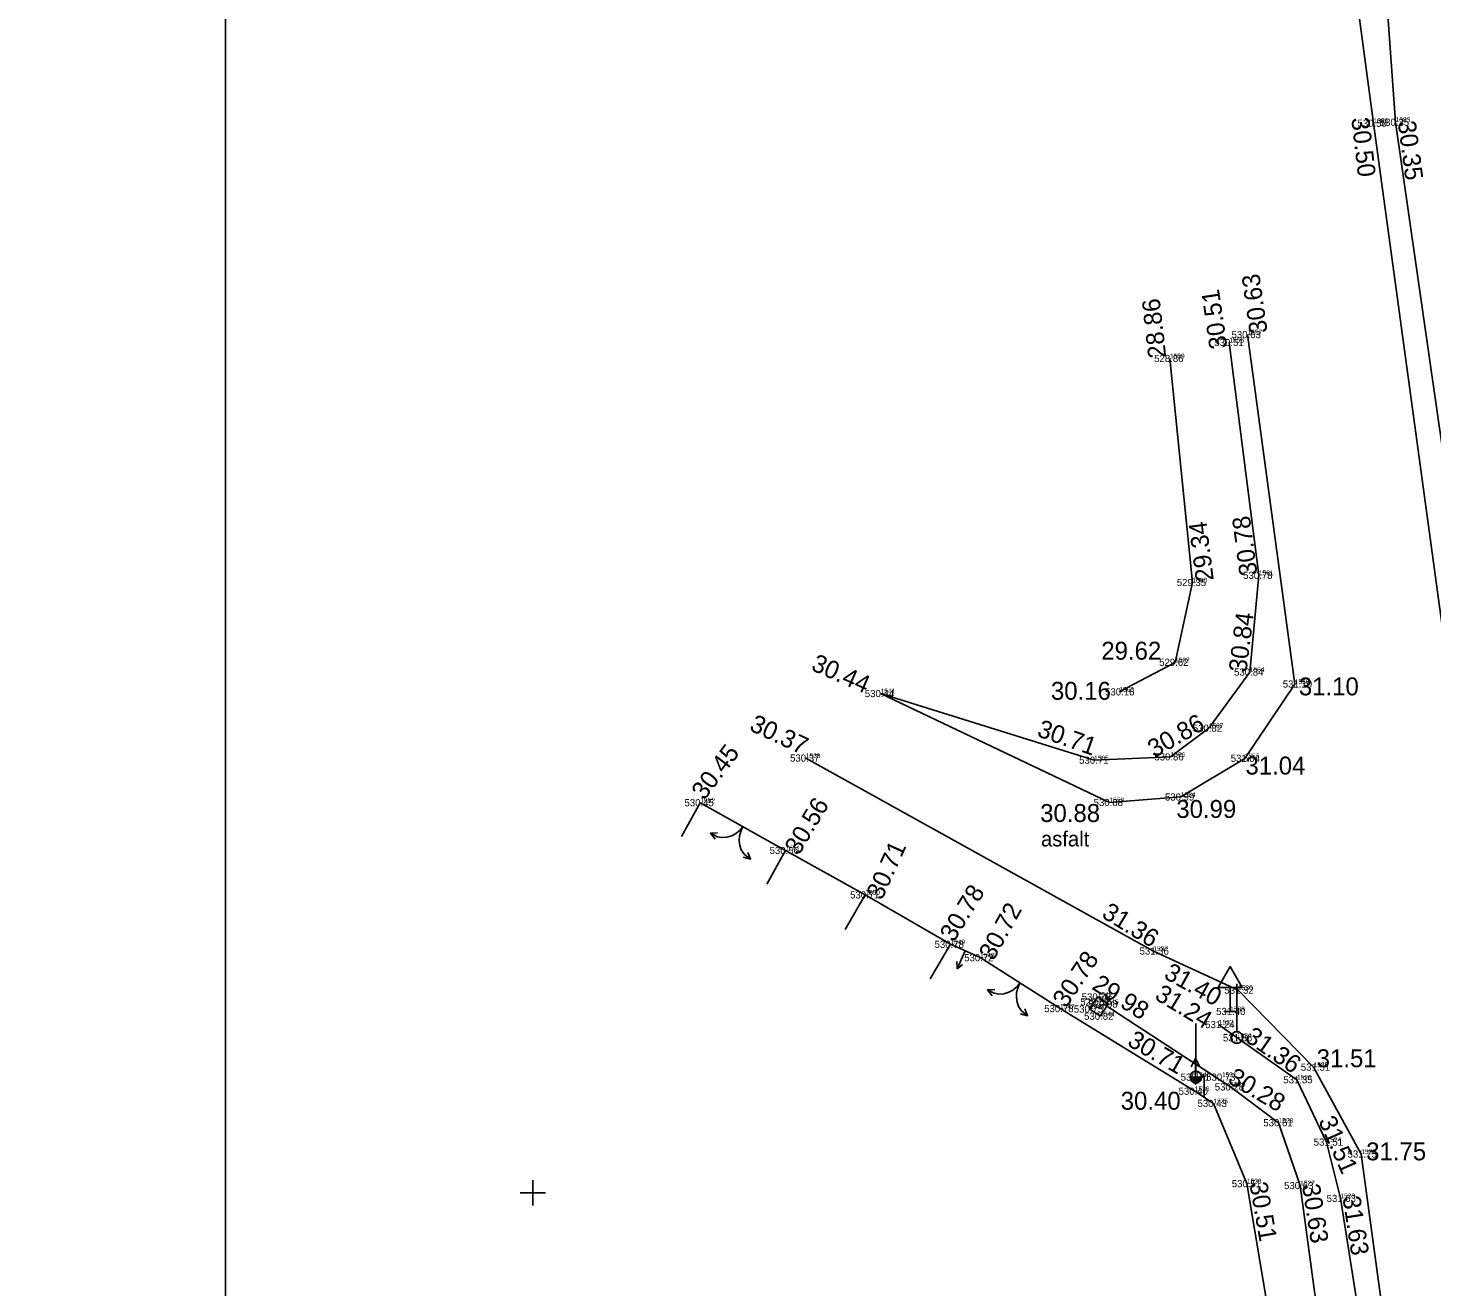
# Model space of a CAD drawing. Extents: x -866693 to -866303, y -1041966 to -1040244.
# Drawn here: x -866521.1 to -866462.4, y -1041903.9 to -1041851.2 of the extents above; entities that cross this region are included whole.
import ezdxf

# ---------------------------------------------------------------- set-up
doc = ezdxf.new("R2010")
doc.units = 0
for name, color, linetype in [('1 hrana zpevněné komunikace-plocha', 7, 'Continuous'), ('10 plot drátěný', 7, 'Continuous'), ('31 budova zděná', 7, 'Continuous'), ('32 stavba bez rozlišení', 7, 'Continuous'), ('33 vstup', 7, 'Continuous'), ('34 vrata-vjezd', 7, 'Continuous'), ('38 sloup dřevěný', 7, 'Continuous'), ('39 sloup betonový', 7, 'Continuous'), ('42 dopravní značka', 7, 'Continuous'), ('44 PRIS', 7, 'Continuous'), ('56 přítokové nebo odtokové potrubí', 7, 'Continuous'), ('7 hrana svah nahoře', 7, 'Continuous'), ('8 hrana svah dole', 7, 'Continuous'), ('9 plot dřevěný', 7, 'Continuous'), ('Bod', 7, 'Continuous'), ('Formát', 7, 'Continuous'), ('Nadmořská výška', 7, 'Continuous'), ('Nadmořská výška_tisk', 7, 'Continuous'), ('popisy', 7, 'Continuous'), ('Síť křížek', 7, 'Continuous'), ('Číslo bodu', 7, 'Continuous')]:
    doc.layers.add(name, color=color, linetype=linetype)

msp = doc.modelspace()

# ---------------------------------------------------------------- linework, layer by layer
at = {"layer": '1 hrana zpevněné komunikace-plocha'}
for points in [[(-866521.136, -1041445.078), (-866508.392, -1041537.454), (-866498.773, -1041606.69), (-866494.1, -1041640.595), (-866489.402, -1041674.676), (-866486.72, -1041694.284), (-866486.072, -1041699.754), (-866485.271, -1041705.651), (-866480.766, -1041738.663), (-866470.416, -1041813.512), (-866469.678, -1041818.801), (-866468.328, -1041828.98), (-866464.804, -1041855.208), (-866460.868, -1041884.031), (-866456.109, -1041894.798), (-866454.046, -1041896.659), (-866450.549, -1041899.657), (-866442.256, -1041905.958), (-866433.526, -1041913.041), (-866423.347, -1041921.351)], [(-866485.44, -1041879.086), (-866475.862, -1041883.647), (-866472.872, -1041883.42), (-866470.196, -1041881.804), (-866468.096, -1041878.694), (-866470.077, -1041864.06)], [(-866458.763, -1041945.697), (-866463.007, -1041915.39), (-866465.316, -1041898.37), (-866467.312, -1041894.734), (-866470.477, -1041891.508), (-866474.022, -1041889.87), (-866488.573, -1041881.791)]]:
    msp.add_lwpolyline(points, dxfattribs=at)
at = {"layer": '10 plot drátěný'}
for p, q in [((-866470.107, -1041899.606), (-866471.508, -1041896.249)), ((-866467.474, -1041915.319), (-866470.107, -1041899.606))]:
    msp.add_line(p, q, dxfattribs=at)
at = {"layer": '31 budova zděná'}
for p, q in [((-866492.992, -1041883.662), (-866493.781, -1041885.073)), ((-866492.337, -1041884.028), (-866492.992, -1041883.662)), ((-866489.422, -1041885.658), (-866490.206, -1041887.065)), ((-866489.422, -1041885.658), (-866490.077, -1041885.292)), ((-866486.085, -1041887.518), (-866489.422, -1041885.658)), ((-866486.085, -1041887.518), (-866486.929, -1041888.97)), ((-866482.522, -1041889.589), (-866486.085, -1041887.518)), ((-866482.522, -1041889.589), (-866483.366, -1041891.041))]:
    msp.add_line(p, q, dxfattribs=at)
at = {"layer": '32 stavba bez rozlišení'}
for p, q in [((-866476.692, -1041892.297), (-866476.355, -1041891.789)), ((-866476.692, -1041892.297), (-866476.256, -1041892.603)), ((-866476.355, -1041891.789), (-866475.919, -1041892.095)), ((-866476.256, -1041892.603), (-866475.919, -1041892.095))]:
    msp.add_line(p, q, dxfattribs=at)
at = {"layer": '33 vstup'}
for p, q in [((-866481.28, -1041890.147), (-866482.522, -1041889.589)), ((-866482.242, -1041890.619), (-866481.901, -1041889.868)), ((-866482.242, -1041890.619), (-866482.254, -1041890.308)), ((-866482.242, -1041890.619), (-866482.016, -1041890.429))]:
    msp.add_line(p, q, dxfattribs=at)
at = {"layer": '34 vrata-vjezd'}
for p, q in [((-866492.337, -1041884.028), (-866490.077, -1041885.292)), ((-866477.93, -1041892.283), (-866481.28, -1041890.147))]:
    msp.add_line(p, q, dxfattribs=at)
for points in [[(-866490.889, -1041886.02), (-866491.141, -1041885.824), (-866491.274, -1041885.632), (-866491.33, -1041885.451), (-866491.357, -1041885.247), (-866491.348, -1041885.048), (-866491.284, -1041884.827), (-866491.206, -1041884.658), (-866491.322, -1041884.803), (-866491.498, -1041884.949), (-866491.677, -1041885.042), (-866491.88, -1041885.105), (-866492.091, -1041885.119), (-866492.281, -1041885.083), (-866492.426, -1041885.012), (-866492.57, -1041884.94)], [(-866492.371, -1041885.186), (-866492.57, -1041884.94), (-866492.265, -1041884.927)], [(-866491.196, -1041885.943), (-866490.889, -1041886.02), (-866491.006, -1041885.738)], [(-866479.29, -1041892.577), (-866479.542, -1041892.381), (-866479.674, -1041892.189), (-866479.73, -1041892.008), (-866479.757, -1041891.804), (-866479.749, -1041891.604), (-866479.685, -1041891.384), (-866479.606, -1041891.215), (-866479.723, -1041891.36), (-866479.899, -1041891.505), (-866480.077, -1041891.599), (-866480.281, -1041891.662), (-866480.491, -1041891.676), (-866480.682, -1041891.64), (-866480.826, -1041891.568), (-866480.971, -1041891.497)], [(-866480.772, -1041891.743), (-866480.971, -1041891.497), (-866480.666, -1041891.484)], [(-866479.597, -1041892.499), (-866479.29, -1041892.577), (-866479.407, -1041892.295)]]:
    msp.add_lwpolyline(points, dxfattribs=at)
at = {"layer": '38 sloup dřevěný'}
msp.add_lwpolyline([(-866470.525, -1041893.258), (-866470.45, -1041893.258), (-866470.325, -1041893.348), (-866470.275, -1041893.493), (-866470.325, -1041893.638), (-866470.45, -1041893.728), (-866470.605, -1041893.728), (-866470.73, -1041893.638), (-866470.78, -1041893.493), (-866470.73, -1041893.348), (-866470.605, -1041893.258), (-866470.53, -1041893.258), (-866470.53, -1041891.248)], dxfattribs=at)
at = {"layer": '39 sloup betonový'}
for points in [[(-866472.246, -1041894.908), (-866472.246, -1041892.898)], [(-866472.166, -1041895.388), (-866472.326, -1041895.388), (-866472.446, -1041895.293), (-866472.486, -1041895.148), (-866472.446, -1041895.003), (-866472.326, -1041894.908), (-866472.166, -1041894.908), (-866472.046, -1041895.003), (-866471.996, -1041895.148), (-866472.046, -1041895.293), (-866472.166, -1041895.388), (-866472.366, -1041895.348), (-866472.126, -1041895.348), (-866472.086, -1041895.308), (-866472.406, -1041895.308), (-866472.446, -1041895.268), (-866472.046, -1041895.268), (-866472.046, -1041895.228), (-866472.446, -1041895.228), (-866472.446, -1041895.188), (-866472.046, -1041895.188), (-866472.006, -1041895.148), (-866472.486, -1041895.148)]]:
    msp.add_lwpolyline(points, dxfattribs=at)
at = {"layer": '42 dopravní značka'}
for points in [[(-866470.811, -1041892.398), (-866470.811, -1041891.398), (-866470.311, -1041891.398), (-866470.811, -1041890.523), (-866471.311, -1041891.398), (-866470.811, -1041891.398)], [(-866471.061, -1041892.398), (-866470.561, -1041892.398)]]:
    msp.add_lwpolyline(points, dxfattribs=at)
at = {"layer": '44 PRIS'}
msp.add_line((-866472.286, -1041895.74), (-866471.508, -1041896.249), dxfattribs=at)
for points in [[(-866471.897, -1041895.995), (-866471.897, -1041895.083), (-866472.262, -1041895.448), (-866472.262, -1041894.354), (-866472.444, -1041894.719)], [(-866472.079, -1041894.719), (-866472.262, -1041894.354)]]:
    msp.add_lwpolyline(points, dxfattribs=at)
at = {"layer": '56 přítokové nebo odtokové potrubí'}
msp.add_line((-866476.09, -1041892.091), (-866470.79, -1041895.556), dxfattribs=at)
at = {"layer": '7 hrana svah nahoře'}
for p, q in [((-866463.88, -1041855.165), (-866464.664, -1041844.346)), ((-866459.752, -1041883.969), (-866463.88, -1041855.165)), ((-866470.842, -1041864.392), (-866469.603, -1041874.137)), ((-866469.603, -1041874.137), (-866469.984, -1041878.19)), ((-866469.984, -1041878.19), (-866471.705, -1041880.542)), ((-866476.502, -1041881.884), (-866485.44, -1041879.086)), ((-866471.705, -1041880.542), (-866473.307, -1041881.743)), ((-866473.307, -1041881.743), (-866476.502, -1041881.884)), ((-866468.011, -1041895.26), (-866471.281, -1041892.954)), ((-866466.769, -1041897.87), (-866468.011, -1041895.26)), ((-866466.191, -1041900.225), (-866466.769, -1041897.87)), ((-866463.744, -1041915.502), (-866466.191, -1041900.225))]:
    msp.add_line(p, q, dxfattribs=at)
at = {"layer": '8 hrana svah dole'}
for p, q in [((-866472.389, -1041874.443), (-866473.328, -1041865.059)), ((-866473.116, -1041877.784), (-866472.389, -1041874.443)), ((-866475.448, -1041879.021), (-866473.116, -1041877.784)), ((-866470.79, -1041895.556), (-866468.781, -1041897.063)), ((-866468.781, -1041897.063), (-866467.876, -1041899.685)), ((-866467.876, -1041899.685), (-866465.747, -1041915.31))]:
    msp.add_line(p, q, dxfattribs=at)
at = {"layer": '9 plot dřevěný'}
msp.add_line((-866472.286, -1041895.74), (-866477.93, -1041892.283), dxfattribs=at)
at = {"layer": 'Bod'}
for p, q in [((-866464.804, -1041855.208), (-866464.804, -1041855.208)), ((-866463.88, -1041855.165), (-866463.88, -1041855.165)), ((-866470.077, -1041864.06), (-866470.077, -1041864.06)), ((-866470.842, -1041864.392), (-866470.842, -1041864.392)), ((-866473.328, -1041865.059), (-866473.328, -1041865.059)), ((-866472.389, -1041874.443), (-866472.389, -1041874.443)), ((-866469.603, -1041874.137), (-866469.603, -1041874.137)), ((-866473.116, -1041877.784), (-866473.116, -1041877.784)), ((-866469.984, -1041878.19), (-866469.984, -1041878.19)), ((-866468.096, -1041878.694), (-866468.096, -1041878.694)), ((-866485.44, -1041879.086), (-866485.44, -1041879.086)), ((-866475.448, -1041879.021), (-866475.448, -1041879.021)), ((-866471.705, -1041880.542), (-866471.705, -1041880.542)), ((-866488.573, -1041881.791), (-866488.573, -1041881.791)), ((-866476.502, -1041881.884), (-866476.502, -1041881.884)), ((-866473.307, -1041881.743), (-866473.307, -1041881.743)), ((-866470.196, -1041881.804), (-866470.196, -1041881.804)), ((-866472.872, -1041883.42), (-866472.872, -1041883.42)), ((-866492.992, -1041883.662), (-866492.992, -1041883.662)), ((-866475.862, -1041883.647), (-866475.862, -1041883.647)), ((-866489.422, -1041885.658), (-866489.422, -1041885.658)), ((-866486.085, -1041887.518), (-866486.085, -1041887.518)), ((-866482.522, -1041889.589), (-866482.522, -1041889.589)), ((-866474.022, -1041889.87), (-866474.022, -1041889.87)), ((-866481.28, -1041890.147), (-866481.28, -1041890.147)), ((-866470.477, -1041891.508), (-866470.477, -1041891.508)), ((-866477.93, -1041892.283), (-866477.93, -1041892.283)), ((-866476.692, -1041892.297), (-866476.692, -1041892.297)), ((-866476.429, -1041891.998), (-866476.429, -1041891.998)), ((-866476.355, -1041891.789), (-866476.355, -1041891.789)), ((-866476.09, -1041892.091), (-866476.09, -1041892.091)), ((-866476.256, -1041892.603), (-866476.256, -1041892.603)), ((-866470.811, -1041892.398), (-866470.811, -1041892.398)), ((-866471.281, -1041892.954), (-866471.281, -1041892.954)), ((-866470.525, -1041893.498), (-866470.525, -1041893.498)), ((-866472.246, -1041895.148), (-866472.246, -1041895.148)), ((-866467.312, -1041894.734), (-866467.312, -1041894.734)), ((-866472.286, -1041895.74), (-866472.286, -1041895.74)), ((-866470.79, -1041895.556), (-866470.79, -1041895.556)), ((-866468.011, -1041895.26), (-866468.011, -1041895.26)), ((-866471.508, -1041896.249), (-866471.508, -1041896.249)), ((-866468.781, -1041897.063), (-866468.781, -1041897.063)), ((-866466.769, -1041897.87), (-866466.769, -1041897.87)), ((-866465.316, -1041898.37), (-866465.316, -1041898.37)), ((-866470.107, -1041899.606), (-866470.107, -1041899.606)), ((-866467.876, -1041899.685), (-866467.876, -1041899.685)), ((-866466.191, -1041900.225), (-866466.191, -1041900.225))]:
    msp.add_line(p, q, dxfattribs=at)
at = {"layer": 'Formát'}
msp.add_lwpolyline([(-866512.871, -1041669.147), (-866302.871, -1041669.147), (-866302.871, -1041966.147), (-866512.871, -1041966.147)], close=True, dxfattribs=at)
at = {"layer": 'Síť křížek'}
for p, q in [((-866500, -1041900.53), (-866500, -1041899.47)), ((-866500.53, -1041900), (-866499.47, -1041900))]:
    msp.add_line(p, q, dxfattribs=at)

# ---------------------------------------------------------------- texts
at = {"layer": 'Nadmořská výška'}
for s, p in [('530.50', (-866465.475, -1041855.36)), ('530.35', (-866464.542, -1041855.32)), ('530.63', (-866470.75, -1041864.21)), ('530.51', (-866471.469, -1041864.54)), ('528.86', (-866473.988, -1041865.21)), ('530.78', (-866470.262, -1041874.29)), ('529.35', (-866473.041, -1041874.59)), ('529.62', (-866473.779, -1041877.93)), ('530.84', (-866470.642, -1041878.34)), ('531.10', (-866468.604, -1041878.84)), ('530.44', (-866486.102, -1041879.24)), ('530.16', (-866476.041, -1041879.17)), ('530.82', (-866472.372, -1041880.69)), ('530.37', (-866489.232, -1041881.94)), ('530.71', (-866477.129, -1041882.03)), ('530.86', (-866473.98, -1041881.89)), ('531.04', (-866470.783, -1041881.95)), ('530.88', (-866476.522, -1041883.8)), ('530.99', (-866473.535, -1041883.57)), ('530.45', (-866493.652, -1041883.81)), ('530.56', (-866490.09, -1041885.81)), ('530.71', (-866486.719, -1041887.67)), ('530.78', (-866483.182, -1041889.74)), ('531.36', (-866474.599, -1041890.02)), ('530.72', (-866481.942, -1041890.3)), ('530.73', (-866477.022, -1041891.94)), ('531.32', (-866471.051, -1041891.66)), ('530.78', (-866478.592, -1041892.43)), ('530.75', (-866477.352, -1041892.45)), ('529.87', (-866477.081, -1041892.15)), ('529.98', (-866476.743, -1041892.24)), ('531.40', (-866471.393, -1041892.55)), ('530.82', (-866476.922, -1041892.75)), ('531.24', (-866471.851, -1041893.1)), ('531.36', (-866471.109, -1041893.65)), ('531.51', (-866467.848, -1041894.88)), ('530.71', (-866472.879, -1041895.3)), ('530.73', (-866471.812, -1041895.3)), ('531.35', (-866468.581, -1041895.41)), ('530.40', (-866472.965, -1041895.89)), ('530.28', (-866471.452, -1041895.71)), ('530.43', (-866472.172, -1041896.4)), ('530.61', (-866469.417, -1041897.21)), ('531.51', (-866467.308, -1041898.02)), ('531.75', (-866465.891, -1041898.52)), ('530.51', (-866470.739, -1041899.76)), ('530.63', (-866468.55, -1041899.84)), ('531.63', (-866466.769, -1041900.38))]:
    msp.add_text(s, height=0.3, dxfattribs=at).set_placement(p)
at = {"layer": 'Nadmořská výška_tisk'}
for s, rotation, p in [('30.50', 276.62949, (-866465.736, -1041855.001)), ('30.35', 277.56188, (-866463.79, -1041855.149)), ('30.63', 98.04541, (-866469.238, -1041863.962)), ('30.51', 98.34011, (-866470.918, -1041864.611)), ('28.86', 96.47317, (-866473.48, -1041865.009)), ('30.78', 97.45717, (-866469.664, -1041874.102)), ('29.34', 97.20037, (-866471.491, -1041874.338)), ('30.84', 82.83795, (-866470.127, -1041878.229)), ('30.44', 336.1995, (-866488.394, -1041878.089)), ('30.86', 29.62613, (-866473.987, -1041881.793)), ('30.37', 334.97301, (-866490.979, -1041880.612)), ('30.71', 340.63276, (-866478.932, -1041880.865)), ('30.45', 53.14275, (-866492.821, -1041883.586)), ('30.56', 59.15739, (-866488.865, -1041885.893)), ('30.71', 65.62353, (-866485.388, -1041887.773)), ('30.78', 58.21498, (-866482.378, -1041889.528)), ('30.72', 61.01756, (-866480.718, -1041890.316)), ('31.36', 328.30586, (-866476.23, -1041888.433)), ('30.78', 56.20422, (-866477.674, -1041892.287)), ('31.40', 330.99387, (-866473.629, -1041890.985)), ('29.98', 327.65791, (-866476.64, -1041891.438)), ('31.24', 328.88693, (-866474.011, -1041891.863)), ('30.71', 329.8615, (-866475.158, -1041893.797)), ('31.36', 325.31847, (-866470.24, -1041893.604)), ('30.28', 329.52294, (-866470.955, -1041895.359)), ('31.51', 293.75739, (-866467.124, -1041896.975)), ('30.51', 279.92887, (-866470.003, -1041899.599)), ('30.63', 278.7422, (-866467.8, -1041899.669)), ('31.63', 278.7422, (-866466.106, -1041900.179))]:
    msp.add_text(s, height=0.75, rotation=rotation, dxfattribs=at).set_placement(p)
for s, p in [('29.62', (-866476.202, -1041877.671)), ('30.16', (-866478.311, -1041879.351)), ('31.10', (-866467.93, -1041879.165)), ('31.04', (-866470.167, -1041882.48)), ('30.88', (-866478.762, -1041884.467)), ('30.99', (-866473.062, -1041884.297)), ('31.51', (-866467.183, -1041894.734)), ('30.40', (-866475.39, -1041896.515)), ('31.75', (-866465.111, -1041898.634))]:
    msp.add_text(s, height=0.75, dxfattribs=at).set_placement(p)
at = {"layer": 'popisy'}
msp.add_text('asfalt', height=0.632, dxfattribs=at).set_placement((-866478.727, -1041885.491))
at = {"layer": 'Číslo bodu'}
for s, p in [('1382', (-866464.804, -1041855.208)), ('1383', (-866463.88, -1041855.165)), ('1557', (-866470.077, -1041864.06)), ('1558', (-866470.842, -1041864.392)), ('1559', (-866473.328, -1041865.059)), ('1561', (-866469.603, -1041874.137)), ('1560', (-866472.389, -1041874.443)), ('1562', (-866473.116, -1041877.784)), ('1564', (-866469.984, -1041878.19)), ('1556', (-866468.096, -1041878.694)), ('1541', (-866485.44, -1041879.086)), ('1563', (-866475.448, -1041879.021)), ('1567', (-866471.705, -1041880.542)), ('1539', (-866488.573, -1041881.791)), ('1565', (-866476.502, -1041881.884)), ('1566', (-866473.307, -1041881.743)), ('1555', (-866470.196, -1041881.804)), ('1552', (-866492.992, -1041883.662)), ('1553', (-866475.862, -1041883.647)), ('1554', (-866472.872, -1041883.42)), ('1551', (-866489.422, -1041885.658)), ('1550', (-866486.085, -1041887.518)), ('1549', (-866482.522, -1041889.589)), ('1548', (-866481.28, -1041890.147)), ('1537', (-866474.022, -1041889.87)), ('1542', (-866476.355, -1041891.789)), ('1530', (-866470.477, -1041891.508)), ('1547', (-866477.93, -1041892.283)), ('1543', (-866476.692, -1041892.297)), ('1546', (-866476.429, -1041891.998)), ('1545', (-866476.09, -1041892.091)), ('1533', (-866470.811, -1041892.398)), ('1544', (-866476.256, -1041892.603)), ('1532', (-866471.281, -1041892.954)), ('1534', (-866470.525, -1041893.498)), ('1525', (-866467.312, -1041894.734)), ('1540', (-866472.246, -1041895.148)), ('1531', (-866471.151, -1041895.151)), ('1526', (-866468.011, -1041895.26)), ('1536', (-866472.286, -1041895.74)), ('1529', (-866470.79, -1041895.556)), ('1535', (-866471.508, -1041896.249)), ('1528', (-866468.781, -1041897.063)), ('1524', (-866466.769, -1041897.87)), ('1522', (-866465.316, -1041898.37)), ('1538', (-866470.107, -1041899.606)), ('1527', (-866467.876, -1041899.685)), ('1523', (-866466.191, -1041900.225))]:
    msp.add_text(s, height=0.2, dxfattribs=at).set_placement(p)

doc.saveas('drawing.dxf')
